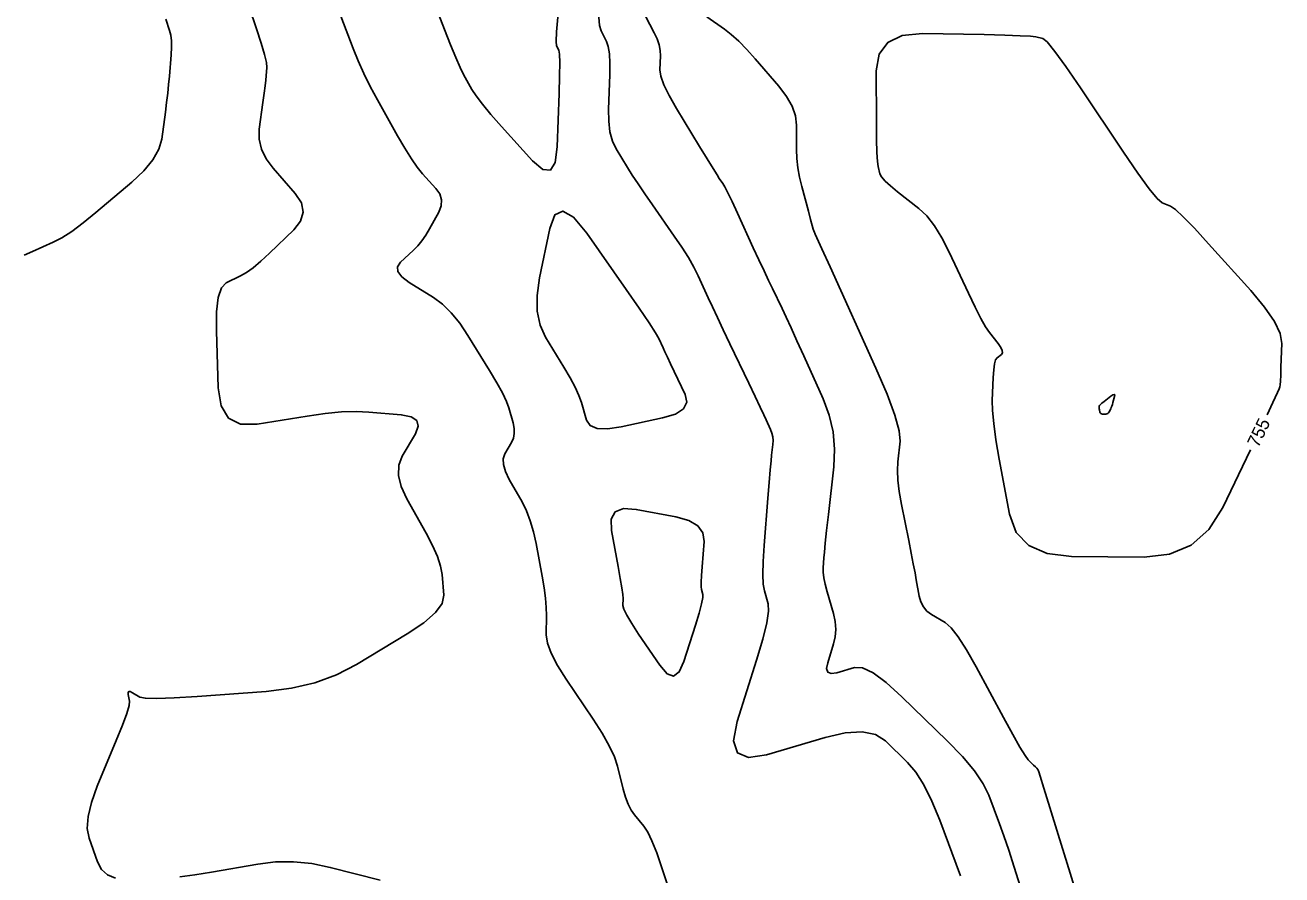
# Model space of a CAD drawing. Extents: x 2082232 to 2083549, y 592624 to 593832.
# Drawn here: x 2082545.3 to 2082613.4, y 592778.4 to 592824.4 of the extents above; entities that cross this region are included whole.
import ezdxf

# ---------------------------------------------------------------- set-up
doc = ezdxf.new("R2010")
doc.units = 0
doc.layers.add('DT_X_Contour_Major', color=7, linetype='Continuous')
doc.layers.add('DT_X_Contour_Minor', color=7, linetype='Continuous')

msp = doc.modelspace()

# ---------------------------------------------------------------- linework, layer by layer
at = {"layer": 'DT_X_Contour_Major'}
for points in [[(2082591.492, 592816.733), (2082591.456, 592816.994), (2082591.43, 592817.479), (2082591.412, 592818.187), (2082591.404, 592819.119), (2082591.395, 592821.9), (2082591.549, 592822.809), (2082592.017, 592823.451), (2082592.8, 592823.827), (2082593.897, 592823.935), (2082597.243, 592823.867), (2082598.358, 592823.84), (2082599.196, 592823.812), (2082599.756, 592823.783), (2082600.037, 592823.751), (2082600.418, 592823.665), (2082600.652, 592823.474), (2082601.069, 592822.964), (2082601.669, 592822.136), (2082602.453, 592820.99), (2082604.786, 592817.509), (2082605.574, 592816.358), (2082606.185, 592815.516), (2082606.622, 592814.984), (2082606.882, 592814.76), (2082607.343, 592814.575), (2082607.601, 592814.396), (2082608.031, 592813.996), (2082608.632, 592813.376), (2082609.404, 592812.535), (2082611.691, 592809.999), (2082612.439, 592809.107), (2082612.969, 592808.332), (2082613.279, 592807.674), (2082613.371, 592807.133), (2082613.323, 592805.846), (2082613.306, 592805.418), (2082613.291, 592805.101), (2082613.277, 592804.894), (2082613.265, 592804.798), (2082613.233, 592804.688), (2082613.142, 592804.482), (2082612.89, 592803.946), (2082612.569, 592803.269)], [(2082611.664, 592801.374), (2082610.169, 592798.252), (2082609.415, 592797.063), (2082608.454, 592796.218), (2082607.287, 592795.717), (2082605.913, 592795.562), (2082601.976, 592795.606), (2082600.658, 592795.76), (2082599.658, 592796.192), (2082598.975, 592796.9), (2082598.61, 592797.884), (2082598.059, 592800.878), (2082597.881, 592801.919), (2082597.759, 592802.796), (2082597.693, 592803.508), (2082597.683, 592804.056), (2082597.733, 592805.3), (2082597.76, 592805.716), (2082597.804, 592806.033), (2082597.865, 592806.25), (2082597.944, 592806.368), (2082598.175, 592806.549), (2082598.229, 592806.636), (2082598.218, 592806.763), (2082598.14, 592806.929), (2082597.997, 592807.134), (2082597.527, 592807.733), (2082597.324, 592808.034), (2082597.068, 592808.489), (2082596.758, 592809.097), (2082596.394, 592809.858), (2082595.353, 592812.091), (2082594.957, 592812.866), (2082594.55, 592813.517), (2082594.132, 592814.044), (2082593.704, 592814.446), (2082592.547, 592815.353), (2082592.162, 592815.669), (2082591.876, 592815.938), (2082591.688, 592816.159), (2082591.599, 592816.333), (2082591.492, 592816.733)]]:
    msp.add_lwpolyline(points, dxfattribs=at)
at = {"layer": 'DT_X_Contour_Minor'}
for points in [[(2082557.037, 592826.496), (2082557.823, 592824.181), (2082558.079, 592823.4), (2082558.258, 592822.792), (2082558.36, 592822.357), (2082558.384, 592822.096), (2082558.345, 592821.63), (2082558.324, 592821.409), (2082558.287, 592821.096), (2082558.235, 592820.691), (2082558.169, 592820.194), (2082557.973, 592818.745), (2082557.965, 592818.205), (2082558.087, 592817.673), (2082558.34, 592817.149), (2082558.723, 592816.632), (2082559.92, 592815.264), (2082560.251, 592814.756), (2082560.348, 592814.258), (2082560.209, 592813.769), (2082559.836, 592813.29), (2082558.529, 592812.026), (2082558.063, 592811.594), (2082557.646, 592811.244), (2082557.278, 592810.978), (2082556.959, 592810.795), (2082556.175, 592810.419), (2082555.922, 592810.15), (2082555.751, 592809.629), (2082555.662, 592808.854), (2082555.656, 592807.825), (2082555.75, 592804.743), (2082555.908, 592803.753), (2082556.311, 592803.093), (2082556.96, 592802.763), (2082557.855, 592802.764), (2082560.569, 592803.206), (2082561.541, 592803.344), (2082562.423, 592803.427), (2082563.214, 592803.454), (2082563.915, 592803.425), (2082565.662, 592803.274), (2082566.202, 592803.167), (2082566.51, 592802.961), (2082566.588, 592802.654), (2082566.434, 592802.246), (2082565.716, 592801.027), (2082565.53, 592800.54), (2082565.509, 592799.992), (2082565.654, 592799.384), (2082565.964, 592798.717), (2082567.013, 592796.856), (2082567.362, 592796.193), (2082567.622, 592795.599), (2082567.793, 592795.075), (2082567.876, 592794.62), (2082567.978, 592793.498), (2082567.882, 592793.053), (2082567.518, 592792.556), (2082566.887, 592792.009), (2082565.987, 592791.411), (2082563.231, 592789.748), (2082562.151, 592789.19), (2082560.978, 592788.761), (2082559.712, 592788.462), (2082558.353, 592788.292), (2082554.605, 592788.013), (2082553.356, 592787.933), (2082552.423, 592787.901), (2082551.804, 592787.917), (2082551.501, 592787.981), (2082551.11, 592788.217), (2082550.985, 592788.278), (2082550.904, 592788.282), (2082550.866, 592788.23), (2082550.871, 592788.122), (2082550.944, 592787.759), (2082550.919, 592787.524), (2082550.791, 592787.09), (2082550.559, 592786.458), (2082550.223, 592785.627), (2082549.191, 592783.149), (2082548.873, 592782.276), (2082548.694, 592781.516), (2082548.653, 592780.869), (2082548.751, 592780.336), (2082549.198, 592779.063), (2082549.419, 592778.647), (2082549.746, 592778.352), (2082550.179, 592778.178)], [(2082574.154, 592824.821), (2082574.081, 592824.014), (2082574.056, 592823.494), (2082574.079, 592823.261), (2082574.201, 592823.025), (2082574.236, 592822.812), (2082574.251, 592822.351), (2082574.244, 592821.642), (2082574.217, 592820.684), (2082574.116, 592817.799), (2082574.004, 592816.94), (2082573.744, 592816.526), (2082573.335, 592816.557), (2082572.778, 592817.033), (2082571.095, 592818.897), (2082570.522, 592819.546), (2082570.064, 592820.097), (2082569.721, 592820.549), (2082569.494, 592820.902), (2082569.041, 592821.712), (2082568.849, 592822.092), (2082568.611, 592822.625), (2082568.329, 592823.311), (2082568.002, 592824.15), (2082567.068, 592826.59)], [(2082580.58, 592776.353), (2082579.788, 592778.736), (2082579.504, 592779.547), (2082579.247, 592780.192), (2082579.017, 592780.671), (2082578.814, 592780.984), (2082578.308, 592781.599), (2082578.127, 592781.859), (2082577.965, 592782.178), (2082577.82, 592782.556), (2082577.694, 592782.993), (2082577.382, 592784.237), (2082577.212, 592784.747), (2082576.934, 592785.341), (2082576.549, 592786.022), (2082576.057, 592786.787), (2082574.602, 592788.944), (2082574.125, 592789.701), (2082573.786, 592790.354), (2082573.584, 592790.905), (2082573.52, 592791.352), (2082573.532, 592792.406), (2082573.521, 592792.835), (2082573.478, 592793.332), (2082573.403, 592793.896), (2082573.296, 592794.528), (2082572.969, 592796.302), (2082572.83, 592796.941), (2082572.656, 592797.529), (2082572.448, 592798.066), (2082572.206, 592798.551), (2082571.516, 592799.776), (2082571.306, 592800.207), (2082571.195, 592800.58), (2082571.182, 592800.896), (2082571.268, 592801.154), (2082571.629, 592801.767), (2082571.736, 592802.006), (2082571.788, 592802.263), (2082571.785, 592802.539), (2082571.726, 592802.834), (2082571.495, 592803.644), (2082571.364, 592803.999), (2082571.145, 592804.456), (2082570.839, 592805.015), (2082570.444, 592805.677), (2082569.275, 592807.576), (2082568.829, 592808.238), (2082568.37, 592808.8), (2082567.897, 592809.261), (2082567.41, 592809.622), (2082566.093, 592810.45), (2082565.693, 592810.752), (2082565.481, 592811.035), (2082565.456, 592811.299), (2082565.62, 592811.546), (2082566.306, 592812.178), (2082566.554, 592812.428), (2082566.785, 592812.705), (2082566.999, 592813.009), (2082567.196, 592813.34), (2082567.696, 592814.257), (2082567.827, 592814.595), (2082567.843, 592814.922), (2082567.746, 592815.237), (2082567.534, 592815.541), (2082566.817, 592816.334), (2082566.531, 592816.686), (2082566.21, 592817.146), (2082565.854, 592817.715), (2082565.463, 592818.392), (2082564.374, 592820.341), (2082563.985, 592821.062), (2082563.636, 592821.766), (2082563.326, 592822.45), (2082563.055, 592823.116), (2082562.385, 592824.868)], [(2082576.376, 592824.815), (2082576.407, 592824.361), (2082576.491, 592824.067), (2082576.786, 592823.498), (2082576.879, 592823.225), (2082576.939, 592822.832), (2082576.965, 592822.318), (2082576.958, 592821.684), (2082576.893, 592819.834), (2082576.901, 592819.18), (2082576.972, 592818.603), (2082577.108, 592818.105), (2082577.307, 592817.685), (2082577.924, 592816.669), (2082578.181, 592816.256), (2082578.492, 592815.781), (2082578.855, 592815.243), (2082579.271, 592814.643), (2082580.45, 592812.958), (2082580.862, 592812.349), (2082581.216, 592811.787), (2082581.509, 592811.272), (2082581.744, 592810.804), (2082582.29, 592809.618), (2082582.517, 592809.128), (2082582.789, 592808.55), (2082583.106, 592807.882), (2082583.467, 592807.124), (2082584.491, 592804.986), (2082584.837, 592804.26), (2082585.11, 592803.687), (2082585.309, 592803.265), (2082585.433, 592802.996), (2082585.666, 592802.48), (2082585.739, 592802.284), (2082585.785, 592802.083), (2082585.803, 592801.877), (2082585.793, 592801.665), (2082585.729, 592801.094), (2082585.699, 592800.787), (2082585.655, 592800.294), (2082585.599, 592799.615), (2082585.531, 592798.751), (2082585.33, 592796.198), (2082585.274, 592795.327), (2082585.256, 592794.627), (2082585.276, 592794.1), (2082585.334, 592793.744), (2082585.54, 592793.025), (2082585.559, 592792.633), (2082585.46, 592791.996), (2082585.244, 592791.115), (2082584.911, 592789.989), (2082583.865, 592786.661), (2082583.671, 592785.612), (2082583.871, 592784.963), (2082584.467, 592784.712), (2082585.457, 592784.861), (2082588.623, 592785.788), (2082589.719, 592786.038), (2082590.629, 592786.091), (2082591.355, 592785.948), (2082591.897, 592785.609), (2082593.095, 592784.443), (2082593.541, 592783.919), (2082593.98, 592783.221), (2082594.412, 592782.351), (2082594.838, 592781.307), (2082595.963, 592778.292)], [(2082599.202, 592777.732), (2082598.875, 592778.774), (2082598.579, 592779.684), (2082598.315, 592780.463), (2082598.082, 592781.111), (2082597.502, 592782.663), (2082597.197, 592783.285), (2082596.717, 592783.984), (2082596.061, 592784.761), (2082595.23, 592785.617), (2082592.78, 592788.002), (2082591.931, 592788.771), (2082591.221, 592789.29), (2082590.65, 592789.559), (2082590.219, 592789.578), (2082589.254, 592789.296), (2082588.953, 592789.251), (2082588.771, 592789.327), (2082588.71, 592789.525), (2082588.77, 592789.844), (2082589.088, 592790.858), (2082589.177, 592791.246), (2082589.204, 592791.65), (2082589.169, 592792.069), (2082589.073, 592792.503), (2082588.736, 592793.682), (2082588.627, 592794.095), (2082588.554, 592794.448), (2082588.516, 592794.743), (2082588.515, 592794.978), (2082588.558, 592795.527), (2082588.586, 592795.829), (2082588.636, 592796.32), (2082588.71, 592797.002), (2082588.806, 592797.875), (2082589.095, 592800.456), (2082589.14, 592801.413), (2082589.059, 592802.345), (2082588.853, 592803.254), (2082588.522, 592804.138), (2082587.47, 592806.466), (2082587.1, 592807.281), (2082586.781, 592807.979), (2082586.511, 592808.561), (2082586.292, 592809.025), (2082585.773, 592810.11), (2082585.562, 592810.553), (2082585.319, 592811.071), (2082585.044, 592811.662), (2082584.737, 592812.328), (2082583.874, 592814.2), (2082583.583, 592814.828), (2082583.354, 592815.305), (2082583.188, 592815.632), (2082583.085, 592815.809), (2082582.895, 592816.08), (2082582.775, 592816.265), (2082582.556, 592816.616), (2082582.239, 592817.133), (2082581.823, 592817.816), (2082580.583, 592819.859), (2082580.177, 592820.565), (2082579.891, 592821.151), (2082579.722, 592821.617), (2082579.673, 592821.962), (2082579.7, 592822.724), (2082579.687, 592823.017), (2082579.627, 592823.322), (2082579.522, 592823.64), (2082579.37, 592823.972), (2082578.904, 592824.873)], [(2082602.621, 592776.12), (2082601.252, 592780.545), (2082600.801, 592782.001), (2082600.476, 592783.05), (2082600.275, 592783.693), (2082600.2, 592783.93), (2082600.166, 592784.02), (2082600.142, 592784.063), (2082600.092, 592784.125), (2082600.018, 592784.205), (2082599.92, 592784.303), (2082599.624, 592784.591), (2082599.457, 592784.815), (2082599.18, 592785.269), (2082598.79, 592785.954), (2082598.29, 592786.871), (2082596.807, 592789.622), (2082596.286, 592790.545), (2082595.834, 592791.252), (2082595.451, 592791.742), (2082595.138, 592792.016), (2082594.396, 592792.456), (2082594.145, 592792.642), (2082593.949, 592792.87), (2082593.808, 592793.14), (2082593.722, 592793.451), (2082593.566, 592794.337), (2082593.497, 592794.72), (2082593.405, 592795.202), (2082593.291, 592795.784), (2082593.155, 592796.466), (2082592.762, 592798.419), (2082592.639, 592799.112), (2082592.564, 592799.727), (2082592.539, 592800.265), (2082592.561, 592800.725), (2082592.687, 592801.849), (2082592.64, 592802.411), (2082592.406, 592803.257), (2082591.986, 592804.385), (2082591.378, 592805.796), (2082588.892, 592811.297), (2082588.452, 592812.272), (2082588.185, 592812.861), (2082588.093, 592813.065), (2082588.072, 592813.108), (2082588.055, 592813.145), (2082588.012, 592813.238), (2082587.985, 592813.323), (2082587.927, 592813.529), (2082587.838, 592813.855), (2082587.718, 592814.3), (2082587.357, 592815.648), (2082587.238, 592816.152), (2082587.153, 592816.653), (2082587.101, 592817.152), (2082587.083, 592817.649), (2082587.078, 592818.97), (2082587.017, 592819.473), (2082586.837, 592819.99), (2082586.537, 592820.523), (2082586.118, 592821.07), (2082584.843, 592822.55), (2082584.379, 592823.066), (2082583.946, 592823.507), (2082583.542, 592823.873), (2082583.168, 592824.162), (2082582.212, 592824.833)], [(2082552.907, 592824.704), (2082553.113, 592824.096), (2082553.177, 592823.842), (2082553.212, 592823.537), (2082553.219, 592823.181), (2082553.197, 592822.774), (2082553.101, 592821.621), (2082553.061, 592821.174), (2082553.011, 592820.699), (2082552.951, 592820.197), (2082552.882, 592819.666), (2082552.685, 592818.213), (2082552.529, 592817.659), (2082552.208, 592817.086), (2082551.723, 592816.494), (2082551.073, 592815.884), (2082549.12, 592814.231), (2082548.427, 592813.666), (2082547.811, 592813.209), (2082547.273, 592812.86), (2082546.813, 592812.62), (2082545.691, 592812.123), (2082545.229, 592811.922)], [(2082573.705, 592813.375), (2082573.987, 592814.112), (2082574.415, 592814.313), (2082574.992, 592813.977), (2082575.716, 592813.105), (2082577.845, 592810.064), (2082578.554, 592809.042), (2082579.085, 592808.259), (2082579.438, 592807.714), (2082579.613, 592807.408), (2082579.844, 592806.908), (2082579.947, 592806.687), (2082580.083, 592806.397), (2082580.254, 592806.038), (2082580.457, 592805.611), (2082581.046, 592804.382), (2082581.134, 592803.956), (2082580.958, 592803.601), (2082580.517, 592803.317), (2082579.811, 592803.103), (2082577.577, 592802.627), (2082576.831, 592802.515), (2082576.269, 592802.537), (2082575.891, 592802.693), (2082575.697, 592802.983), (2082575.426, 592803.934), (2082575.291, 592804.322), (2082575.087, 592804.772), (2082574.816, 592805.284), (2082574.477, 592805.858), (2082573.483, 592807.473), (2082573.183, 592808.128), (2082573.028, 592808.884), (2082573.018, 592809.739), (2082573.153, 592810.694), (2082573.705, 592813.375)], [(2082603.484, 592803.549), (2082603.476, 592803.595), (2082603.471, 592803.634), (2082603.468, 592803.666), (2082603.467, 592803.69), (2082603.469, 592803.745), (2082603.487, 592803.777), (2082603.538, 592803.829), (2082603.624, 592803.903), (2082603.742, 592803.998), (2082604.104, 592804.281), (2082604.219, 592804.359), (2082604.291, 592804.381), (2082604.322, 592804.348), (2082604.31, 592804.259), (2082604.221, 592803.948), (2082604.189, 592803.838), (2082604.157, 592803.743), (2082604.127, 592803.661), (2082604.097, 592803.594), (2082604.02, 592803.433), (2082603.987, 592803.38), (2082603.944, 592803.343), (2082603.893, 592803.321), (2082603.832, 592803.314), (2082603.657, 592803.316), (2082603.599, 592803.323), (2082603.555, 592803.342), (2082603.524, 592803.373), (2082603.508, 592803.417), (2082603.484, 592803.549)], [(2082577.055, 592797.001), (2082577.038, 592797.619), (2082577.256, 592798.016), (2082577.708, 592798.193), (2082578.395, 592798.151), (2082580.539, 592797.745), (2082581.237, 592797.547), (2082581.724, 592797.258), (2082582.001, 592796.879), (2082582.066, 592796.408), (2082581.957, 592795.032), (2082581.925, 592794.569), (2082581.911, 592794.21), (2082581.913, 592793.955), (2082581.932, 592793.806), (2082582.006, 592793.546), (2082582.002, 592793.369), (2082581.932, 592793.032), (2082581.798, 592792.534), (2082581.599, 592791.877), (2082580.981, 592789.911), (2082580.725, 592789.345), (2082580.42, 592789.121), (2082580.066, 592789.241), (2082579.664, 592789.703), (2082578.524, 592791.391), (2082578.15, 592791.963), (2082577.884, 592792.413), (2082577.724, 592792.739), (2082577.672, 592792.943), (2082577.677, 592793.323), (2082577.662, 592793.539), (2082577.612, 592793.901), (2082577.529, 592794.409), (2082577.412, 592795.063), (2082577.055, 592797.001)], [(2082553.659, 592778.246), (2082554.472, 592778.353), (2082555.375, 592778.499), (2082557.899, 592778.94), (2082558.854, 592779.053), (2082559.825, 592779.059), (2082560.813, 592778.96), (2082561.818, 592778.754), (2082564.519, 592778.065)]]:
    msp.add_lwpolyline(points, dxfattribs=at)

# ---------------------------------------------------------------- texts
at = {"layer": 'DT_X_Contour_Major'}
msp.add_text('755', height=0.7, rotation=64.46819, dxfattribs=at).set_placement((2082612.091, 592801.457))

doc.saveas('drawing.dxf')
